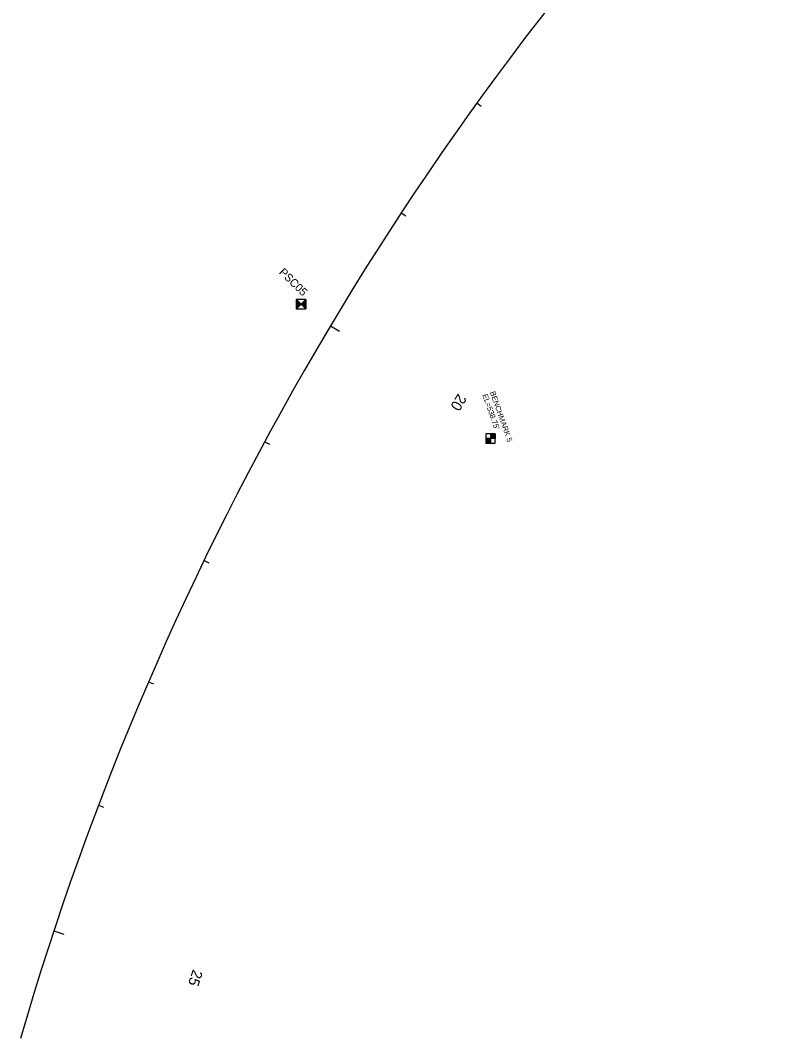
# Model space of a CAD drawing. Extents: x 2004390 to 2008791, y 1133870 to 1140084.
# Drawn here: x 2007673 to 2008236, y 1138550 to 1139314 of the extents above; entities that cross this region are included whole.
import ezdxf

# ---------------------------------------------------------------- set-up
doc = ezdxf.new("R2010")
doc.units = 0
for name, color, linetype in [('RD_HC_Cl', 7, 'Continuous'), ('RD_HC_Data_Tic', 7, 'Continuous'), ('RD_HC_Survey', 7, 'Continuous'), ('RD_HC_Survey_txCode', 7, 'Continuous'), ('RD_HC_TX_Sta50', 7, 'Continuous')]:
    doc.layers.add(name, color=color, linetype=linetype)

msp = doc.modelspace()

# ---------------------------------------------------------------- linework, layer by layer
at = {"layer": 'RD_HC_Cl'}
msp.add_arc((2009873.97, 1137910.41), 2292.01, 135.62222, 163.79147, dxfattribs=at)
at = {"layer": 'RD_HC_Data_Tic'}
for p, q in [((2008015.49, 1139251.81), (2008018.73, 1139249.47)), ((2007958.75, 1139169.47), (2007962.09, 1139167.28)), ((2007905.66, 1139084.74), (2007912.53, 1139080.64)), ((2007856.31, 1138997.77), (2007859.83, 1138995.88)), ((2007810.81, 1138908.74), (2007814.41, 1138906.99)), ((2007769.23, 1138817.8), (2007772.9, 1138816.22)), ((2007731.65, 1138725.14), (2007735.39, 1138723.71)), ((2007698.16, 1138630.92), (2007705.75, 1138628.41))]:
    msp.add_line(p, q, dxfattribs=at)
at = {"layer": 'RD_HC_Survey'}
for p, q in [((2007880.04, 1139104.43), (2007887.12, 1139097.36)), ((2007887.12, 1139104.43), (2007880.04, 1139097.36)), ((2007880.09, 1139104.38), (2007880.09, 1139097.41)), ((2007880.14, 1139104.33), (2007880.14, 1139097.46)), ((2007880.19, 1139104.28), (2007880.19, 1139097.51)), ((2007880.24, 1139104.23), (2007880.24, 1139097.56)), ((2007880.29, 1139104.18), (2007880.29, 1139097.61)), ((2007880.34, 1139104.13), (2007880.34, 1139097.66)), ((2007880.39, 1139104.08), (2007880.39, 1139097.71)), ((2007880.44, 1139104.03), (2007880.44, 1139097.76)), ((2007880.49, 1139103.98), (2007880.49, 1139097.81)), ((2007880.54, 1139103.93), (2007880.54, 1139097.86)), ((2007880.59, 1139103.88), (2007880.59, 1139097.91)), ((2007880.64, 1139103.83), (2007880.64, 1139097.96)), ((2007880.69, 1139103.78), (2007880.69, 1139098.01)), ((2007880.74, 1139103.73), (2007880.74, 1139098.06)), ((2007880.79, 1139103.68), (2007880.79, 1139098.11)), ((2007880.84, 1139103.63), (2007880.84, 1139098.16)), ((2007880.89, 1139103.58), (2007880.89, 1139098.21)), ((2007880.94, 1139103.53), (2007880.94, 1139098.26)), ((2007880.99, 1139103.48), (2007880.99, 1139098.31)), ((2007881.04, 1139103.43), (2007881.04, 1139098.36)), ((2007881.09, 1139103.38), (2007881.09, 1139098.41)), ((2007881.14, 1139103.33), (2007881.14, 1139098.46)), ((2007881.19, 1139103.28), (2007881.19, 1139098.51)), ((2007881.24, 1139103.23), (2007881.24, 1139098.56)), ((2007881.29, 1139103.18), (2007881.29, 1139098.61)), ((2007881.34, 1139103.13), (2007881.34, 1139098.66)), ((2007881.39, 1139103.08), (2007881.39, 1139098.71)), ((2007881.44, 1139103.03), (2007881.44, 1139098.76)), ((2007881.49, 1139102.98), (2007881.49, 1139098.81)), ((2007881.54, 1139102.93), (2007881.54, 1139098.86)), ((2007881.59, 1139102.88), (2007881.59, 1139098.91)), ((2007881.64, 1139102.83), (2007881.64, 1139098.96)), ((2007881.69, 1139102.78), (2007881.69, 1139099.01)), ((2007881.74, 1139102.73), (2007881.74, 1139099.06)), ((2007881.79, 1139102.68), (2007881.79, 1139099.11)), ((2007881.84, 1139102.63), (2007881.84, 1139099.16)), ((2007881.89, 1139102.58), (2007881.89, 1139099.21)), ((2007881.94, 1139102.53), (2007881.94, 1139099.26)), ((2007881.99, 1139102.48), (2007881.99, 1139099.31)), ((2007882.04, 1139102.43), (2007882.04, 1139099.36)), ((2007882.09, 1139102.38), (2007882.09, 1139099.41)), ((2007882.14, 1139102.33), (2007882.14, 1139099.46)), ((2007882.19, 1139102.28), (2007882.19, 1139099.51)), ((2007882.24, 1139102.23), (2007882.24, 1139099.56)), ((2007882.29, 1139102.18), (2007882.29, 1139099.61)), ((2007882.34, 1139102.13), (2007882.34, 1139099.66)), ((2007882.39, 1139102.08), (2007882.39, 1139099.71)), ((2007882.44, 1139102.03), (2007882.44, 1139099.76)), ((2007882.49, 1139101.98), (2007882.49, 1139099.81)), ((2007882.54, 1139101.93), (2007882.54, 1139099.86)), ((2007882.59, 1139101.88), (2007882.59, 1139099.91)), ((2007882.64, 1139101.83), (2007882.64, 1139099.96)), ((2007882.69, 1139101.78), (2007882.69, 1139100.01)), ((2007882.74, 1139101.73), (2007882.74, 1139100.06)), ((2007882.79, 1139101.68), (2007882.79, 1139100.11)), ((2007882.84, 1139101.63), (2007882.84, 1139100.16)), ((2007882.89, 1139101.58), (2007882.89, 1139100.21)), ((2007882.94, 1139101.53), (2007882.94, 1139100.26)), ((2007882.99, 1139101.48), (2007882.99, 1139100.31)), ((2007883.04, 1139101.43), (2007883.04, 1139100.36)), ((2007883.09, 1139101.38), (2007883.09, 1139100.41)), ((2007883.14, 1139101.33), (2007883.14, 1139100.46)), ((2007883.19, 1139101.28), (2007883.19, 1139100.51)), ((2007883.24, 1139101.23), (2007883.24, 1139100.56)), ((2007883.29, 1139101.18), (2007883.29, 1139100.61)), ((2007883.34, 1139101.13), (2007883.34, 1139100.66)), ((2007883.39, 1139101.08), (2007883.39, 1139100.71)), ((2007883.44, 1139101.03), (2007883.44, 1139100.76)), ((2007883.49, 1139100.98), (2007883.49, 1139100.81)), ((2007883.54, 1139100.93), (2007883.54, 1139100.86)), ((2007883.62, 1139100.93), (2007883.62, 1139100.86)), ((2007883.67, 1139100.98), (2007883.67, 1139100.81)), ((2007883.72, 1139101.03), (2007883.72, 1139100.76)), ((2007883.77, 1139101.08), (2007883.77, 1139100.71)), ((2007883.82, 1139101.13), (2007883.82, 1139100.66)), ((2007883.87, 1139101.18), (2007883.87, 1139100.61)), ((2007883.92, 1139101.23), (2007883.92, 1139100.56)), ((2007883.97, 1139101.28), (2007883.97, 1139100.51)), ((2007884.02, 1139101.33), (2007884.02, 1139100.46)), ((2007884.07, 1139101.38), (2007884.07, 1139100.41)), ((2007884.12, 1139101.43), (2007884.12, 1139100.36)), ((2007884.17, 1139101.48), (2007884.17, 1139100.31)), ((2007884.22, 1139101.53), (2007884.22, 1139100.26)), ((2007884.27, 1139101.58), (2007884.27, 1139100.21)), ((2007884.32, 1139101.63), (2007884.32, 1139100.16)), ((2007884.37, 1139101.68), (2007884.37, 1139100.11)), ((2007884.42, 1139101.73), (2007884.42, 1139100.06)), ((2007884.47, 1139101.78), (2007884.47, 1139100.01)), ((2007884.52, 1139101.83), (2007884.52, 1139099.96)), ((2007884.57, 1139101.88), (2007884.57, 1139099.91)), ((2007884.62, 1139101.93), (2007884.62, 1139099.86)), ((2007884.67, 1139101.98), (2007884.67, 1139099.81)), ((2007884.72, 1139102.03), (2007884.72, 1139099.76)), ((2007884.77, 1139102.08), (2007884.77, 1139099.71)), ((2007884.82, 1139102.13), (2007884.82, 1139099.66)), ((2007884.87, 1139102.18), (2007884.87, 1139099.61)), ((2007884.92, 1139102.23), (2007884.92, 1139099.56)), ((2007884.97, 1139102.28), (2007884.97, 1139099.51)), ((2007885.02, 1139102.33), (2007885.02, 1139099.46)), ((2007885.07, 1139102.38), (2007885.07, 1139099.41)), ((2007885.12, 1139102.43), (2007885.12, 1139099.36)), ((2007885.17, 1139102.48), (2007885.17, 1139099.31)), ((2007885.22, 1139102.53), (2007885.22, 1139099.26)), ((2007885.27, 1139102.58), (2007885.27, 1139099.21)), ((2007885.32, 1139102.63), (2007885.32, 1139099.16)), ((2007885.37, 1139102.68), (2007885.37, 1139099.11)), ((2007885.42, 1139102.73), (2007885.42, 1139099.06)), ((2007885.47, 1139102.78), (2007885.47, 1139099.01)), ((2007885.52, 1139102.83), (2007885.52, 1139098.96)), ((2007885.57, 1139102.88), (2007885.57, 1139098.91)), ((2007885.62, 1139102.93), (2007885.62, 1139098.86)), ((2007885.67, 1139102.98), (2007885.67, 1139098.81)), ((2007885.72, 1139103.03), (2007885.72, 1139098.76)), ((2007885.77, 1139103.08), (2007885.77, 1139098.71)), ((2007885.82, 1139103.13), (2007885.82, 1139098.66)), ((2007885.87, 1139103.18), (2007885.87, 1139098.61)), ((2007885.92, 1139103.23), (2007885.92, 1139098.56)), ((2007885.97, 1139103.28), (2007885.97, 1139098.51)), ((2007886.02, 1139103.33), (2007886.02, 1139098.46)), ((2007886.07, 1139103.38), (2007886.07, 1139098.41)), ((2007886.12, 1139103.43), (2007886.12, 1139098.36)), ((2007886.17, 1139103.48), (2007886.17, 1139098.31)), ((2007886.22, 1139103.53), (2007886.22, 1139098.26)), ((2007886.27, 1139103.58), (2007886.27, 1139098.21)), ((2007886.32, 1139103.63), (2007886.32, 1139098.16)), ((2007886.37, 1139103.68), (2007886.37, 1139098.11)), ((2007886.42, 1139103.73), (2007886.42, 1139098.06)), ((2007886.47, 1139103.78), (2007886.47, 1139098.01)), ((2007886.52, 1139103.83), (2007886.52, 1139097.96)), ((2007886.57, 1139103.88), (2007886.57, 1139097.91)), ((2007886.62, 1139103.93), (2007886.62, 1139097.86)), ((2007886.67, 1139103.98), (2007886.67, 1139097.81)), ((2007886.72, 1139104.03), (2007886.72, 1139097.76)), ((2007886.77, 1139104.08), (2007886.77, 1139097.71)), ((2007886.82, 1139104.13), (2007886.82, 1139097.66)), ((2007886.87, 1139104.18), (2007886.87, 1139097.61)), ((2007886.92, 1139104.23), (2007886.92, 1139097.56)), ((2007886.97, 1139104.28), (2007886.97, 1139097.51)), ((2007887.02, 1139104.33), (2007887.02, 1139097.46)), ((2007887.07, 1139104.38), (2007887.07, 1139097.41)), ((2008029.26, 1139000.25), (2008022.19, 1139000.25)), ((2008022.19, 1139000.25), (2008022.19, 1138996.72)), ((2008022.24, 1139000.25), (2008022.24, 1138996.72)), ((2008022.29, 1139000.25), (2008022.29, 1138996.72)), ((2008022.34, 1139000.25), (2008022.34, 1138996.72)), ((2008022.39, 1139000.25), (2008022.39, 1138996.72)), ((2008022.44, 1139000.25), (2008022.44, 1138996.72)), ((2008022.49, 1139000.25), (2008022.49, 1138996.72)), ((2008022.54, 1139000.25), (2008022.54, 1138996.72)), ((2008022.59, 1139000.25), (2008022.59, 1138996.72)), ((2008022.64, 1139000.25), (2008022.64, 1138996.72)), ((2008022.69, 1139000.25), (2008022.69, 1138996.72)), ((2008022.74, 1139000.25), (2008022.74, 1138996.72)), ((2008022.79, 1139000.25), (2008022.79, 1138996.72)), ((2008022.84, 1139000.25), (2008022.84, 1138996.72)), ((2008022.89, 1139000.25), (2008022.89, 1138996.72)), ((2008022.94, 1139000.25), (2008022.94, 1138996.72)), ((2008022.99, 1139000.25), (2008022.99, 1138996.72)), ((2008023.04, 1139000.25), (2008023.04, 1138996.72)), ((2008023.09, 1139000.25), (2008023.09, 1138996.72)), ((2008023.14, 1139000.25), (2008023.14, 1138996.72)), ((2008023.19, 1139000.25), (2008023.19, 1138996.72)), ((2008023.24, 1139000.25), (2008023.24, 1138996.72)), ((2008023.29, 1139000.25), (2008023.29, 1138996.72)), ((2008023.34, 1139000.25), (2008023.34, 1138996.72)), ((2008023.39, 1139000.25), (2008023.39, 1138996.72)), ((2008023.44, 1139000.25), (2008023.44, 1138996.72)), ((2008023.49, 1139000.25), (2008023.49, 1138996.72)), ((2008023.54, 1139000.25), (2008023.54, 1138996.72)), ((2008023.59, 1139000.25), (2008023.59, 1138996.72)), ((2008023.64, 1139000.25), (2008023.64, 1138996.72)), ((2008023.69, 1139000.25), (2008023.69, 1138996.72)), ((2008023.74, 1139000.25), (2008023.74, 1138996.72)), ((2008023.79, 1139000.25), (2008023.79, 1138996.72)), ((2008023.84, 1139000.25), (2008023.84, 1138996.72)), ((2008023.89, 1139000.25), (2008023.89, 1138996.72)), ((2008023.94, 1139000.25), (2008023.94, 1138996.72)), ((2008023.99, 1139000.25), (2008023.99, 1138996.72)), ((2008024.04, 1139000.25), (2008024.04, 1138996.72)), ((2008024.09, 1139000.25), (2008024.09, 1138996.72)), ((2008024.14, 1139000.25), (2008024.14, 1138996.72)), ((2008024.19, 1139000.25), (2008024.19, 1138996.72)), ((2008024.24, 1139000.25), (2008024.24, 1138996.72)), ((2008024.29, 1139000.25), (2008024.29, 1138996.72)), ((2008024.34, 1139000.25), (2008024.34, 1138996.72)), ((2008024.39, 1139000.25), (2008024.39, 1138996.72)), ((2008024.44, 1139000.25), (2008024.44, 1138996.72)), ((2008024.49, 1139000.25), (2008024.49, 1138996.72)), ((2008024.54, 1139000.25), (2008024.54, 1138996.72)), ((2008024.59, 1139000.25), (2008024.59, 1138996.72)), ((2008024.64, 1139000.25), (2008024.64, 1138996.72)), ((2008024.69, 1139000.25), (2008024.69, 1138996.72)), ((2008024.74, 1139000.25), (2008024.74, 1138996.72)), ((2008024.79, 1139000.25), (2008024.79, 1138996.72)), ((2008024.84, 1139000.25), (2008024.84, 1138996.72)), ((2008024.89, 1139000.25), (2008024.89, 1138996.72)), ((2008024.94, 1139000.25), (2008024.94, 1138996.72)), ((2008024.99, 1139000.25), (2008024.99, 1138996.72)), ((2008025.04, 1139000.25), (2008025.04, 1138996.72)), ((2008025.09, 1139000.25), (2008025.09, 1138996.72)), ((2008025.14, 1139000.25), (2008025.14, 1138996.72)), ((2008025.19, 1139000.25), (2008025.19, 1138996.72)), ((2008025.24, 1139000.25), (2008025.24, 1138996.72)), ((2008025.29, 1139000.25), (2008025.29, 1138996.72)), ((2008025.34, 1139000.25), (2008025.34, 1138996.72)), ((2008025.39, 1139000.25), (2008025.39, 1138996.72)), ((2008025.44, 1139000.25), (2008025.44, 1138996.72)), ((2008025.49, 1139000.25), (2008025.49, 1138996.72)), ((2008025.54, 1139000.25), (2008025.54, 1138996.72)), ((2008025.59, 1139000.25), (2008025.59, 1138996.72)), ((2008025.64, 1139000.25), (2008025.64, 1138996.72)), ((2008025.69, 1139000.25), (2008025.69, 1138996.72)), ((2008025.73, 1139003.79), (2008025.73, 1138996.72)), ((2008025.76, 1139003.79), (2008025.76, 1139000.25)), ((2008025.81, 1139003.79), (2008025.81, 1139000.25)), ((2008025.86, 1139003.79), (2008025.86, 1139000.25)), ((2008025.91, 1139003.79), (2008025.91, 1139000.25)), ((2008025.96, 1139003.79), (2008025.96, 1139000.25)), ((2008026.01, 1139003.79), (2008026.01, 1139000.25)), ((2008026.06, 1139003.79), (2008026.06, 1139000.25)), ((2008026.11, 1139003.79), (2008026.11, 1139000.25)), ((2008026.16, 1139003.79), (2008026.16, 1139000.25)), ((2008026.21, 1139003.79), (2008026.21, 1139000.25)), ((2008026.26, 1139003.79), (2008026.26, 1139000.25)), ((2008026.31, 1139003.79), (2008026.31, 1139000.25)), ((2008026.36, 1139003.79), (2008026.36, 1139000.25)), ((2008026.41, 1139003.79), (2008026.41, 1139000.25)), ((2008026.46, 1139003.79), (2008026.46, 1139000.25)), ((2008026.51, 1139003.79), (2008026.51, 1139000.25)), ((2008026.56, 1139003.79), (2008026.56, 1139000.25)), ((2008026.61, 1139003.79), (2008026.61, 1139000.25)), ((2008026.66, 1139003.79), (2008026.66, 1139000.25)), ((2008026.71, 1139003.79), (2008026.71, 1139000.25)), ((2008026.76, 1139003.79), (2008026.76, 1139000.25)), ((2008026.81, 1139003.79), (2008026.81, 1139000.25)), ((2008026.86, 1139003.79), (2008026.86, 1139000.25)), ((2008026.91, 1139003.79), (2008026.91, 1139000.25)), ((2008026.96, 1139003.79), (2008026.96, 1139000.25)), ((2008027.01, 1139003.79), (2008027.01, 1139000.25)), ((2008027.06, 1139003.79), (2008027.06, 1139000.25)), ((2008027.11, 1139003.79), (2008027.11, 1139000.25)), ((2008027.16, 1139003.79), (2008027.16, 1139000.25)), ((2008027.21, 1139003.79), (2008027.21, 1139000.25)), ((2008027.26, 1139003.79), (2008027.26, 1139000.25)), ((2008027.31, 1139003.79), (2008027.31, 1139000.25)), ((2008027.36, 1139003.79), (2008027.36, 1139000.25)), ((2008027.41, 1139003.79), (2008027.41, 1139000.25)), ((2008027.46, 1139003.79), (2008027.46, 1139000.25)), ((2008027.51, 1139003.79), (2008027.51, 1139000.25)), ((2008027.56, 1139003.79), (2008027.56, 1139000.25)), ((2008027.61, 1139003.79), (2008027.61, 1139000.25)), ((2008027.66, 1139003.79), (2008027.66, 1139000.25)), ((2008027.71, 1139003.79), (2008027.71, 1139000.25)), ((2008027.76, 1139003.79), (2008027.76, 1139000.25)), ((2008027.81, 1139003.79), (2008027.81, 1139000.25)), ((2008027.86, 1139003.79), (2008027.86, 1139000.25)), ((2008027.91, 1139003.79), (2008027.91, 1139000.25)), ((2008027.96, 1139003.79), (2008027.96, 1139000.25)), ((2008028.01, 1139003.79), (2008028.01, 1139000.25)), ((2008028.06, 1139003.79), (2008028.06, 1139000.25)), ((2008028.11, 1139003.79), (2008028.11, 1139000.25)), ((2008028.16, 1139003.79), (2008028.16, 1139000.25)), ((2008028.21, 1139003.79), (2008028.21, 1139000.25)), ((2008028.26, 1139003.79), (2008028.26, 1139000.25)), ((2008028.31, 1139003.79), (2008028.31, 1139000.25)), ((2008028.36, 1139003.79), (2008028.36, 1139000.25)), ((2008028.41, 1139003.79), (2008028.41, 1139000.25)), ((2008028.46, 1139003.79), (2008028.46, 1139000.25)), ((2008028.51, 1139003.79), (2008028.51, 1139000.25)), ((2008028.56, 1139003.79), (2008028.56, 1139000.25)), ((2008028.61, 1139003.79), (2008028.61, 1139000.25)), ((2008028.66, 1139003.79), (2008028.66, 1139000.25)), ((2008028.71, 1139003.79), (2008028.71, 1139000.25)), ((2008028.76, 1139003.79), (2008028.76, 1139000.25)), ((2008028.81, 1139003.79), (2008028.81, 1139000.25)), ((2008028.86, 1139003.79), (2008028.86, 1139000.25)), ((2008028.91, 1139003.79), (2008028.91, 1139000.25)), ((2008028.96, 1139003.79), (2008028.96, 1139000.25)), ((2008029.01, 1139003.79), (2008029.01, 1139000.25)), ((2008029.06, 1139003.79), (2008029.06, 1139000.25)), ((2008029.11, 1139003.79), (2008029.11, 1139000.25)), ((2008029.16, 1139003.79), (2008029.16, 1139000.25)), ((2008029.21, 1139003.79), (2008029.21, 1139000.25))]:
    msp.add_line(p, q, dxfattribs=at)
for points in [[(2007887.12, 1139104.43), (2007880.04, 1139104.43), (2007880.04, 1139097.36), (2007887.12, 1139097.36)], [(2008029.26, 1139003.79), (2008022.19, 1139003.79), (2008022.19, 1138996.72), (2008029.26, 1138996.72)]]:
    msp.add_lwpolyline(points, close=True, dxfattribs=at)

# ---------------------------------------------------------------- texts
at = {"layer": 'RD_HC_Survey_txCode'}
for s, height, rotation, p in [('PSC05', 6, 315.21395, (2007866.68, 1139124.41)), ("EL=538.75'", 4, 289.44941, (2008019.53, 1139032.82)), ('BENCHMARK 5', 4, 289.44941, (2008025.19, 1139034.81))]:
    msp.add_text(s, height=height, rotation=rotation, dxfattribs=at).set_placement(p)
at = {"layer": 'RD_HC_TX_Sta50'}
for s, rotation, p in [('20', 239.17886, (2008001.38, 1139034.38)), ('25', 251.67789, (2007802.49, 1138602.44))]:
    msp.add_text(s, height=8, rotation=rotation, dxfattribs=at).set_placement(p)

doc.saveas('drawing.dxf')
